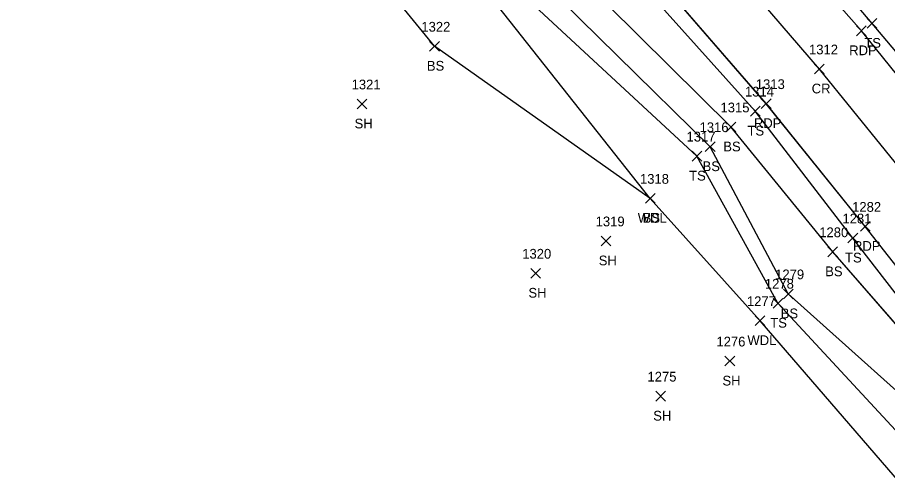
# Model space of a CAD drawing. Extents: x 1415642 to 1422021, y 544543 to 547232.
# Drawn here: x 1416185.4 to 1416364, y 546547.3 to 546640.6 of the extents above; entities that cross this region are included whole.
import ezdxf

# ---------------------------------------------------------------- set-up
doc = ezdxf.new("R2010")
doc.units = 0
for name, color, linetype in [('L_A', 7, 'Continuous'), ('L_I', 7, 'Continuous'), ('L_TIC', 7, 'Continuous'), ('LAWA', 7, 'Continuous'), ('LELB', 7, 'Continuous'), ('P_A', 7, 'Continuous'), ('P_I', 7, 'Continuous'), ('P_TIC', 7, 'Continuous'), ('PET', 7, 'Continuous'), ('PRC', 7, 'Continuous')]:
    doc.layers.add(name, color=color, linetype=linetype)

msp = doc.modelspace()

# ---------------------------------------------------------------- linework, layer by layer
at = {"layer": 'L_TIC'}
for points in [[(1416359.8, 546638.39), (1416361.8, 546640.39)], [(1416361.8, 546638.39), (1416359.8, 546640.39)], [(1416269.97, 546633.69), (1416271.97, 546635.69)], [(1416271.97, 546633.69), (1416269.97, 546635.69)], [(1416255.08, 546621.85), (1416257.08, 546623.85)], [(1416257.08, 546621.85), (1416255.08, 546623.85)], [(1416335.82, 546620.39), (1416337.82, 546622.39)], [(1416337.82, 546620.39), (1416335.82, 546622.39)], [(1416330.82, 546617.14), (1416332.82, 546619.14)], [(1416332.82, 546617.14), (1416330.82, 546619.14)], [(1416326.57, 546613.09), (1416328.57, 546615.09)], [(1416328.57, 546613.09), (1416326.57, 546615.09)], [(1416323.84, 546611.16), (1416325.84, 546613.16)], [(1416325.84, 546611.16), (1416323.84, 546613.16)], [(1416314.28, 546602.5), (1416316.28, 546604.5)], [(1416316.28, 546602.5), (1416314.28, 546604.5)], [(1416314.28, 546602.5), (1416316.28, 546604.5)], [(1416316.28, 546602.5), (1416314.28, 546604.5)], [(1416305.2, 546593.77), (1416307.2, 546595.77)], [(1416307.2, 546593.77), (1416305.2, 546595.77)], [(1416355.85, 546594.36), (1416357.85, 546596.36)], [(1416357.85, 546594.36), (1416355.85, 546596.36)], [(1416351.74, 546591.54), (1416353.74, 546593.54)], [(1416353.74, 546591.54), (1416351.74, 546593.54)], [(1416290.77, 546587.14), (1416292.77, 546589.14)], [(1416292.77, 546587.14), (1416290.77, 546589.14)], [(1416342.61, 546582.91), (1416344.61, 546584.91)], [(1416344.61, 546582.91), (1416342.61, 546584.91)], [(1416340.49, 546580.99), (1416342.49, 546582.99)], [(1416342.49, 546580.99), (1416340.49, 546582.99)], [(1416336.81, 546577.41), (1416338.81, 546579.41)], [(1416338.81, 546577.41), (1416336.81, 546579.41)], [(1416330.6, 546569.13), (1416332.6, 546571.13)], [(1416332.6, 546569.13), (1416330.6, 546571.13)], [(1416316.39, 546561.94), (1416318.39, 546563.94)], [(1416318.39, 546561.94), (1416316.39, 546563.94)]]:
    msp.add_lwpolyline(points, dxfattribs=at)
at = {"layer": 'LAWA'}
for points in [[(1416366.86, 546544.85), (1416337.81, 546578.41), (1416315.28, 546603.5), (1416281.6, 546646.05), (1416263.12, 546671.71), (1416234.79, 546698.48), (1416216.66, 546718.21), (1416189.47, 546748.09), (1416170.48, 546756.81)], [(1416366.86, 546544.85), (1416337.81, 546578.41), (1416315.28, 546603.5), (1416281.6, 546646.05), (1416263.12, 546671.71), (1416234.8, 546698.48), (1416216.66, 546718.21), (1416189.46, 546748.09), (1416170.49, 546756.81)]]:
    msp.add_lwpolyline(points, dxfattribs=at)
at = {"layer": 'LELB'}
for points in [[(1416413.88, 546519.84), (1416385.73, 546558.12), (1416356.85, 546595.36), (1416336.82, 546621.39), (1416300.66, 546661.66), (1416278.22, 546684.25), (1416249.88, 546714.04), (1416230.93, 546728.9), (1416221.86, 546737.5), (1416200.69, 546756.25), (1416176.24, 546778.44), (1416157.26, 546793.38), (1416140.02, 546808.9), (1416121.84, 546825.58), (1416090.2, 546848.7), (1416061.67, 546872.28), (1416021.03, 546902.96), (1415979.27, 546932.57), (1415964.6, 546940.59)], [(1416413.88, 546519.84), (1416385.73, 546558.12), (1416356.85, 546595.36), (1416336.82, 546621.39), (1416300.66, 546661.66), (1416278.22, 546684.25), (1416249.88, 546714.04), (1416230.93, 546728.9), (1416221.87, 546737.51), (1416200.69, 546756.25), (1416176.24, 546778.44), (1416157.26, 546793.38), (1416140.03, 546808.9), (1416121.84, 546825.58), (1416090.21, 546848.7), (1416061.68, 546872.28), (1416021.04, 546902.96), (1415979.28, 546932.57), (1415964.61, 546940.59)], [(1416462.64, 546496.11), (1416437.87, 546538.89), (1416411.19, 546576.82), (1416382.17, 546614.17), (1416360.8, 546639.39), (1416323.65, 546683.15), (1416301.53, 546707.03), (1416273.6, 546735.69), (1416258.67, 546751.22), (1416224.41, 546784.74), (1416201.13, 546806.07), (1416169.09, 546832.26)], [(1416462.64, 546496.11), (1416437.87, 546538.89), (1416411.18, 546576.82), (1416382.17, 546614.17), (1416360.8, 546639.39), (1416323.65, 546683.15), (1416301.53, 546707.03), (1416273.6, 546735.69), (1416258.67, 546751.22), (1416224.4, 546784.74), (1416201.13, 546806.07), (1416169.09, 546832.26)], [(1416578, 546177.77), (1416578.55, 546199.27), (1416573.9, 546214.14), (1416552.43, 546269), (1416536.22, 546304.5), (1416520.22, 546335.71), (1416500.65, 546371.21), (1416484.25, 546405.14), (1416455.06, 546455.78), (1416435.93, 546486.65), (1416412.14, 546519.01), (1416383.64, 546557.13), (1416352.74, 546592.54), (1416331.82, 546618.14), (1416293.94, 546655.61), (1416274.22, 546680.91), (1416245.72, 546708.98), (1416224.27, 546729.93), (1416198.14, 546753.3), (1416170.94, 546765.48), (1416158.5, 546767.31), (1416141.08, 546772.75), (1416136.01, 546776.95), (1416129, 546780.64)], [(1416578, 546177.77), (1416578.55, 546199.27), (1416573.9, 546214.14), (1416552.42, 546269.01), (1416536.22, 546304.5), (1416520.22, 546335.71), (1416500.65, 546371.22), (1416484.25, 546405.15), (1416455.06, 546455.79), (1416435.93, 546486.65), (1416412.14, 546519.01), (1416383.65, 546557.13), (1416352.74, 546592.54), (1416331.82, 546618.14), (1416293.94, 546655.62), (1416274.22, 546680.91), (1416245.72, 546708.98), (1416224.27, 546729.93), (1416198.14, 546753.3), (1416170.94, 546765.48), (1416158.51, 546767.31), (1416141.09, 546772.75), (1416136.01, 546776.96), (1416129.01, 546780.64)], [(1416503.76, 546247.98), (1416498.74, 546274.69), (1416501.23, 546308.66), (1416502.98, 546324.04), (1416489.47, 546365.32), (1416480.57, 546403.46), (1416453.11, 546455.02), (1416433.2, 546484.78), (1416409.26, 546516.78), (1416378.25, 546552.92), (1416343.61, 546583.91), (1416327.57, 546614.09), (1416289.4, 546651.59), (1416267.58, 546675.69), (1416237.14, 546697.31), (1416220.66, 546725.9), (1416195.41, 546750.9), (1416170.78, 546763.33), (1416158.82, 546764.49), (1416140.16, 546770.72), (1416135.4, 546775.05), (1416128.27, 546778.63)], [(1416503.76, 546247.98), (1416498.74, 546274.69), (1416501.24, 546308.65), (1416502.98, 546324.03), (1416489.47, 546365.32), (1416480.57, 546403.46), (1416453.11, 546455.02), (1416433.2, 546484.78), (1416409.26, 546516.79), (1416378.25, 546552.92), (1416343.61, 546583.91), (1416327.58, 546614.09), (1416289.4, 546651.59), (1416267.58, 546675.69), (1416237.14, 546697.31), (1416220.66, 546725.9), (1416195.42, 546750.9), (1416170.78, 546763.33), (1416158.81, 546764.5), (1416140.16, 546770.72), (1416135.4, 546775.05), (1416128.28, 546778.62)], [(1416315.28, 546603.5), (1416270.97, 546634.69), (1416249.08, 546661.51), (1416225.2, 546690.33), (1416216.66, 546718.21)], [(1416315.28, 546603.5), (1416270.97, 546634.69), (1416249.08, 546661.51), (1416225.21, 546690.34), (1416216.66, 546718.21)], [(1416480.57, 546403.46), (1416449.3, 546452.17), (1416431.01, 546483.64), (1416405.55, 546512.84), (1416372.51, 546548.53), (1416341.49, 546581.99), (1416324.84, 546612.16), (1416286, 546648.13), (1416263.12, 546671.71)], [(1416480.57, 546403.46), (1416449.3, 546452.17), (1416431.01, 546483.64), (1416405.56, 546512.84), (1416372.51, 546548.53), (1416341.49, 546581.99), (1416324.84, 546612.16), (1416286, 546648.13), (1416263.12, 546671.71)]]:
    msp.add_lwpolyline(points, dxfattribs=at)
at = {"layer": 'P_TIC'}
for points in [[(1416357.62, 546636.86), (1416359.62, 546638.86)], [(1416359.62, 546636.86), (1416357.62, 546638.86)], [(1416348.98, 546629.03), (1416350.98, 546631.03)], [(1416350.98, 546629.03), (1416348.98, 546631.03)], [(1416338.06, 546621.92), (1416340.06, 546623.92)], [(1416340.06, 546621.92), (1416338.06, 546623.92)], [(1416358.4, 546596.75), (1416360.4, 546598.75)], [(1416360.4, 546596.75), (1416358.4, 546598.75)]]:
    msp.add_lwpolyline(points, dxfattribs=at)
at = {"layer": 'PET'}
for points in [[(1416435.56, 546537.44), (1416408.53, 546574.61), (1416379.54, 546611.97), (1416358.62, 546637.86), (1416320.38, 546681.18), (1416299.04, 546704.62), (1416270.68, 546734.26), (1416256.1, 546749.21), (1416221.42, 546781.44), (1416197.8, 546803.68), (1416167.45, 546829.93), (1416146.9, 546847.39), (1416116.66, 546870.72), (1416088.42, 546892.72), (1416062.97, 546911.59), (1416031.6, 546935.61), (1415998.08, 546959.73), (1415969.06, 546981.93), (1415936.64, 547006.92)], [(1416435.56, 546537.44), (1416408.53, 546574.62), (1416379.54, 546611.97), (1416358.63, 546637.85), (1416320.38, 546681.18), (1416299.04, 546704.62), (1416270.69, 546734.26), (1416256.1, 546749.21), (1416221.42, 546781.44), (1416197.8, 546803.68), (1416167.45, 546829.93), (1416146.9, 546847.38), (1416116.66, 546870.72), (1416088.42, 546892.72), (1416062.98, 546911.58), (1416031.6, 546935.61), (1415998.08, 546959.73), (1415969.07, 546981.93), (1415936.65, 547006.92)], [(1416417.68, 546520.98), (1416388.9, 546560.28), (1416359.4, 546597.75), (1416339.06, 546622.92), (1416303.08, 546664.45), (1416282.37, 546687.64), (1416253.58, 546717.16), (1416237.44, 546733.28), (1416206.51, 546762.17), (1416181.86, 546784.67), (1416151.94, 546810.47), (1416130.39, 546828.26), (1416101.49, 546851.34), (1416072.78, 546874.03), (1416047.41, 546892.82), (1416017.81, 546915.59), (1415982.21, 546942.39), (1415954.4, 546964.56)], [(1416417.68, 546520.98), (1416388.9, 546560.28), (1416359.4, 546597.76), (1416339.06, 546622.93), (1416303.08, 546664.45), (1416282.37, 546687.65), (1416253.58, 546717.16), (1416237.44, 546733.28), (1416206.51, 546762.17), (1416181.87, 546784.67), (1416151.94, 546810.47), (1416130.39, 546828.26), (1416101.49, 546851.34), (1416072.78, 546874.03), (1416047.41, 546892.82), (1416017.81, 546915.59), (1415982.21, 546942.39), (1415954.4, 546964.56)]]:
    msp.add_lwpolyline(points, dxfattribs=at)
at = {"layer": 'PRC'}
for points in [[(1416425.29, 546532.23), (1416399.16, 546568.17), (1416370.34, 546605), (1416349.98, 546630.03), (1416312.55, 546673.44), (1416291.21, 546696.63), (1416262.58, 546725.99), (1416246.66, 546742.06), (1416214.68, 546772.43), (1416190.4, 546794.67), (1416160.38, 546819.82), (1416139.01, 546837.64), (1416109.6, 546860.71), (1416080.51, 546883.13), (1416051.44, 546902.01), (1416024.84, 546926.07), (1415989.92, 546951.67), (1415962.46, 546973.18)], [(1416425.29, 546532.24), (1416399.16, 546568.17), (1416370.35, 546605), (1416349.98, 546630.03), (1416312.55, 546673.45), (1416291.21, 546696.63), (1416262.58, 546725.99), (1416246.66, 546742.06), (1416214.67, 546772.43), (1416190.4, 546794.67), (1416160.38, 546819.82), (1416139.01, 546837.64), (1416109.6, 546860.71), (1416080.51, 546883.13), (1416051.45, 546902.01), (1416024.84, 546926.07), (1415989.92, 546951.68), (1415962.46, 546973.18)]]:
    msp.add_lwpolyline(points, dxfattribs=at)

# ---------------------------------------------------------------- texts
at = {"layer": 'L_A'}
for s, p in [('TS', (1416359.21, 546634.39)), ('BS', (1416269.41, 546629.69)), ('SH', (1416254.57, 546617.85)), ('TS', (1416335.23, 546616.39)), ('BS', (1416330.26, 546613.14)), ('BS', (1416326.01, 546609.09)), ('TS', (1416323.25, 546607.16)), ('WDL', (1416312.7, 546598.5)), ('BS', (1416313.72, 546598.5)), ('SH', (1416304.69, 546589.77)), ('TS', (1416355.26, 546590.36)), ('BS', (1416351.18, 546587.54)), ('SH', (1416290.26, 546583.14)), ('BS', (1416342.05, 546578.91)), ('TS', (1416339.9, 546576.99)), ('WDL', (1416335.22, 546573.41)), ('SH', (1416330.09, 546565.13)), ('SH', (1416315.88, 546557.94))]:
    msp.add_text(s, height=2, dxfattribs=at).set_placement(p)
at = {"layer": 'L_I'}
for s, p in [('1322', (1416268.28, 546637.69)), ('1321', (1416253.96, 546625.85)), ('1314', (1416334.7, 546624.39)), ('1315', (1416329.69, 546621.14)), ('1316', (1416325.39, 546617.09)), ('1317', (1416322.71, 546615.16)), ('1318', (1416313.16, 546606.5)), ('1318', (1416313.16, 546606.5)), ('1281', (1416354.72, 546598.36)), ('1319', (1416304.06, 546597.77)), ('1280', (1416349.96, 546595.54)), ('1320', (1416288.99, 546591.14)), ('1279', (1416340.91, 546586.91)), ('1278', (1416338.8, 546584.99)), ('1277', (1416335.11, 546581.41)), ('1276', (1416328.85, 546573.13)), ('1275', (1416314.7, 546565.94))]:
    msp.add_text(s, height=2, dxfattribs=at).set_placement(p)
at = {"layer": 'P_A'}
for s, p in [('RDP', (1416356.11, 546632.86)), ('CR', (1416348.41, 546625.03)), ('RDP', (1416336.55, 546617.92)), ('RDP', (1416356.89, 546592.75))]:
    msp.add_text(s, height=2, dxfattribs=at).set_placement(p)
at = {"layer": 'P_I'}
for s, p in [('1312', (1416347.86, 546633.03)), ('1313', (1416336.94, 546625.92)), ('1282', (1416356.71, 546600.75))]:
    msp.add_text(s, height=2, dxfattribs=at).set_placement(p)

doc.saveas('drawing.dxf')
